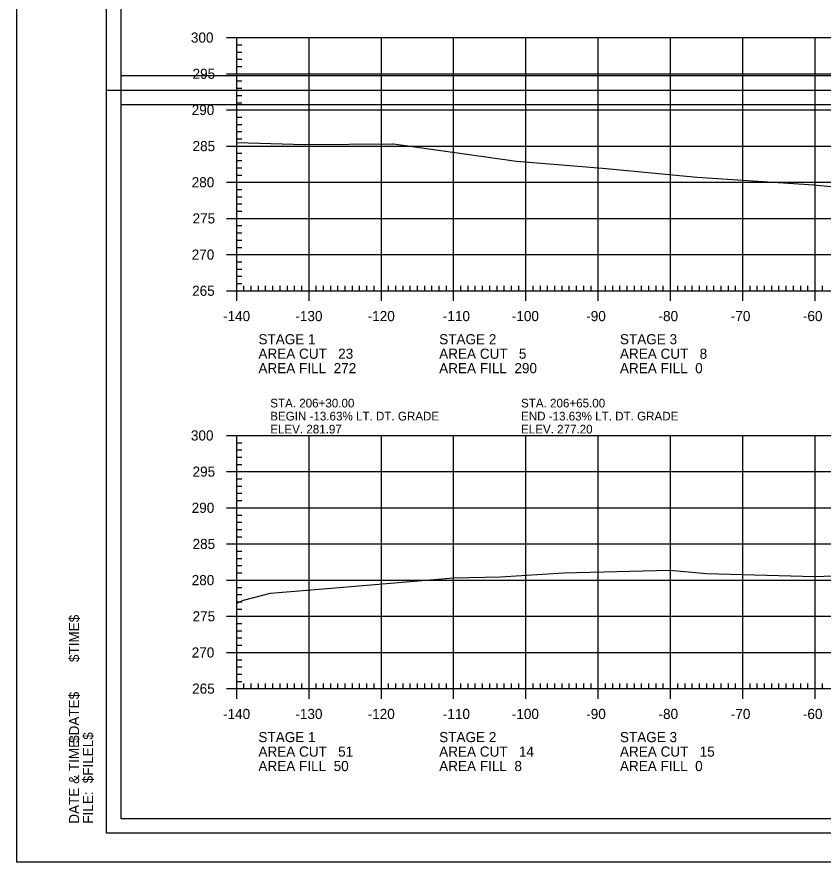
# Model space of a CAD drawing. Extents: x 1368713 to 1370673, y 380279 to 380950.
# Drawn here: x 1370339.2 to 1370450.7, y 380523.8 to 380640.6 of the extents above; entities that cross this region are included whole.
import ezdxf

# ---------------------------------------------------------------- set-up
doc = ezdxf.new("R2010")
doc.units = 0
for name, color, linetype in [('Notes', 7, 'Continuous'), ('R_Axis', 7, 'Continuous'), ('R_Axis Annot', 7, 'Continuous'), ('R_Border', 7, 'Continuous'), ('R_Border Notes', 7, 'Continuous'), ('R_Border Plan-Plan', 7, 'Continuous'), ('R_Exist Surface', 7, 'Continuous'), ('R_Grid', 7, 'Continuous'), ('R_No Plot', 7, 'Continuous')]:
    doc.layers.add(name, color=color, linetype=linetype)

msp = doc.modelspace()

# ---------------------------------------------------------------- linework, layer by layer
at = {"layer": 'R_Axis'}
for p, q in [((1370368.23, 380637.75), (1370371.03, 380637.75)), ((1370369.63, 380602.75), (1370369.63, 380637.75)), ((1370369.63, 380636.75), (1370370.33, 380636.75)), ((1370369.63, 380635.75), (1370370.33, 380635.75)), ((1370369.63, 380634.75), (1370370.33, 380634.75)), ((1370369.63, 380633.75), (1370370.33, 380633.75)), ((1370368.23, 380632.75), (1370371.03, 380632.75)), ((1370369.63, 380631.75), (1370370.33, 380631.75)), ((1370369.63, 380630.75), (1370370.33, 380630.75)), ((1370369.63, 380629.75), (1370370.33, 380629.75)), ((1370369.63, 380628.75), (1370370.33, 380628.75)), ((1370368.23, 380627.75), (1370371.03, 380627.75)), ((1370369.63, 380626.75), (1370370.33, 380626.75)), ((1370369.63, 380625.75), (1370370.33, 380625.75)), ((1370369.63, 380624.75), (1370370.33, 380624.75)), ((1370369.63, 380623.75), (1370370.33, 380623.75)), ((1370368.23, 380622.75), (1370371.03, 380622.75)), ((1370369.63, 380621.75), (1370370.33, 380621.75)), ((1370369.63, 380620.75), (1370370.33, 380620.75)), ((1370369.63, 380619.75), (1370370.33, 380619.75)), ((1370369.63, 380618.75), (1370370.33, 380618.75)), ((1370368.23, 380617.75), (1370371.03, 380617.75)), ((1370369.63, 380616.75), (1370370.33, 380616.75)), ((1370369.63, 380615.75), (1370370.33, 380615.75)), ((1370369.63, 380614.75), (1370370.33, 380614.75)), ((1370369.63, 380613.75), (1370370.33, 380613.75)), ((1370368.23, 380612.75), (1370371.03, 380612.75)), ((1370369.63, 380611.75), (1370370.33, 380611.75)), ((1370369.63, 380610.75), (1370370.33, 380610.75)), ((1370369.63, 380609.75), (1370370.33, 380609.75)), ((1370368.23, 380607.75), (1370371.03, 380607.75)), ((1370369.63, 380608.75), (1370370.33, 380608.75)), ((1370369.63, 380606.75), (1370370.33, 380606.75)), ((1370369.63, 380605.75), (1370370.33, 380605.75)), ((1370369.63, 380604.75), (1370370.33, 380604.75)), ((1370369.63, 380601.35), (1370369.63, 380604.15)), ((1370379.63, 380601.35), (1370379.63, 380604.15)), ((1370389.63, 380601.35), (1370389.63, 380604.15)), ((1370399.63, 380601.35), (1370399.63, 380604.15)), ((1370409.63, 380601.35), (1370409.63, 380604.15)), ((1370419.63, 380601.35), (1370419.63, 380604.15)), ((1370429.63, 380601.35), (1370429.63, 380604.15)), ((1370439.63, 380601.35), (1370439.63, 380604.15)), ((1370449.63, 380601.35), (1370449.63, 380604.15)), ((1370369.63, 380603.75), (1370370.33, 380603.75)), ((1370370.63, 380602.75), (1370370.63, 380603.45)), ((1370371.63, 380602.75), (1370371.63, 380603.45)), ((1370372.63, 380602.75), (1370372.63, 380603.45)), ((1370373.63, 380602.75), (1370373.63, 380603.45)), ((1370374.63, 380602.75), (1370374.63, 380603.45)), ((1370375.63, 380602.75), (1370375.63, 380603.45)), ((1370376.63, 380602.75), (1370376.63, 380603.45)), ((1370377.63, 380602.75), (1370377.63, 380603.45)), ((1370378.63, 380602.75), (1370378.63, 380603.45)), ((1370380.63, 380602.75), (1370380.63, 380603.45)), ((1370381.63, 380602.75), (1370381.63, 380603.45)), ((1370382.63, 380602.75), (1370382.63, 380603.45)), ((1370383.63, 380602.75), (1370383.63, 380603.45)), ((1370384.63, 380602.75), (1370384.63, 380603.45)), ((1370385.63, 380602.75), (1370385.63, 380603.45)), ((1370386.63, 380602.75), (1370386.63, 380603.45)), ((1370387.63, 380602.75), (1370387.63, 380603.45)), ((1370388.63, 380602.75), (1370388.63, 380603.45)), ((1370390.63, 380602.75), (1370390.63, 380603.45)), ((1370391.63, 380602.75), (1370391.63, 380603.45)), ((1370392.63, 380602.75), (1370392.63, 380603.45)), ((1370393.63, 380602.75), (1370393.63, 380603.45)), ((1370394.63, 380602.75), (1370394.63, 380603.45)), ((1370395.63, 380602.75), (1370395.63, 380603.45)), ((1370396.63, 380602.75), (1370396.63, 380603.45)), ((1370397.63, 380602.75), (1370397.63, 380603.45)), ((1370398.63, 380602.75), (1370398.63, 380603.45)), ((1370400.63, 380602.75), (1370400.63, 380603.45)), ((1370401.63, 380602.75), (1370401.63, 380603.45)), ((1370402.63, 380602.75), (1370402.63, 380603.45)), ((1370403.63, 380602.75), (1370403.63, 380603.45)), ((1370404.63, 380602.75), (1370404.63, 380603.45)), ((1370405.63, 380602.75), (1370405.63, 380603.45)), ((1370406.63, 380602.75), (1370406.63, 380603.45)), ((1370407.63, 380602.75), (1370407.63, 380603.45)), ((1370408.63, 380602.75), (1370408.63, 380603.45)), ((1370410.63, 380602.75), (1370410.63, 380603.45)), ((1370411.63, 380602.75), (1370411.63, 380603.45)), ((1370412.63, 380602.75), (1370412.63, 380603.45)), ((1370413.63, 380602.75), (1370413.63, 380603.45)), ((1370414.63, 380602.75), (1370414.63, 380603.45)), ((1370415.63, 380602.75), (1370415.63, 380603.45)), ((1370416.63, 380602.75), (1370416.63, 380603.45)), ((1370417.63, 380602.75), (1370417.63, 380603.45)), ((1370418.63, 380602.75), (1370418.63, 380603.45)), ((1370420.63, 380602.75), (1370420.63, 380603.45)), ((1370421.63, 380602.75), (1370421.63, 380603.45)), ((1370422.63, 380602.75), (1370422.63, 380603.45)), ((1370423.63, 380602.75), (1370423.63, 380603.45)), ((1370424.63, 380602.75), (1370424.63, 380603.45)), ((1370425.63, 380602.75), (1370425.63, 380603.45)), ((1370426.63, 380602.75), (1370426.63, 380603.45)), ((1370427.63, 380602.75), (1370427.63, 380603.45)), ((1370428.63, 380602.75), (1370428.63, 380603.45)), ((1370430.63, 380602.75), (1370430.63, 380603.45)), ((1370431.63, 380602.75), (1370431.63, 380603.45)), ((1370432.63, 380602.75), (1370432.63, 380603.45)), ((1370433.63, 380602.75), (1370433.63, 380603.45)), ((1370434.63, 380602.75), (1370434.63, 380603.45)), ((1370435.63, 380602.75), (1370435.63, 380603.45)), ((1370436.63, 380602.75), (1370436.63, 380603.45)), ((1370437.63, 380602.75), (1370437.63, 380603.45)), ((1370438.63, 380602.75), (1370438.63, 380603.45)), ((1370440.63, 380602.75), (1370440.63, 380603.45)), ((1370441.63, 380602.75), (1370441.63, 380603.45)), ((1370442.63, 380602.75), (1370442.63, 380603.45)), ((1370443.63, 380602.75), (1370443.63, 380603.45)), ((1370444.63, 380602.75), (1370444.63, 380603.45)), ((1370445.63, 380602.75), (1370445.63, 380603.45)), ((1370446.63, 380602.75), (1370446.63, 380603.45)), ((1370447.63, 380602.75), (1370447.63, 380603.45)), ((1370448.63, 380602.75), (1370448.63, 380603.45)), ((1370450.63, 380602.75), (1370450.63, 380603.45)), ((1370368.23, 380602.75), (1370371.03, 380602.75)), ((1370369.63, 380602.75), (1370649.63, 380602.75)), ((1370368.23, 380582.75), (1370371.03, 380582.75)), ((1370369.63, 380547.75), (1370369.63, 380582.75)), ((1370369.63, 380581.75), (1370370.33, 380581.75)), ((1370369.63, 380580.75), (1370370.33, 380580.75)), ((1370369.63, 380579.75), (1370370.33, 380579.75)), ((1370369.63, 380578.75), (1370370.33, 380578.75)), ((1370368.23, 380577.75), (1370371.03, 380577.75)), ((1370369.63, 380576.75), (1370370.33, 380576.75)), ((1370369.63, 380575.75), (1370370.33, 380575.75)), ((1370369.63, 380574.75), (1370370.33, 380574.75)), ((1370368.23, 380572.75), (1370371.03, 380572.75)), ((1370369.63, 380573.75), (1370370.33, 380573.75)), ((1370369.63, 380571.75), (1370370.33, 380571.75)), ((1370369.63, 380570.75), (1370370.33, 380570.75)), ((1370369.63, 380569.75), (1370370.33, 380569.75)), ((1370369.63, 380568.75), (1370370.33, 380568.75)), ((1370368.23, 380567.75), (1370371.03, 380567.75)), ((1370369.63, 380566.75), (1370370.33, 380566.75)), ((1370369.63, 380565.75), (1370370.33, 380565.75)), ((1370369.63, 380564.75), (1370370.33, 380564.75)), ((1370369.63, 380563.75), (1370370.33, 380563.75)), ((1370368.23, 380562.75), (1370371.03, 380562.75)), ((1370369.63, 380561.75), (1370370.33, 380561.75)), ((1370369.63, 380560.75), (1370370.33, 380560.75)), ((1370369.63, 380559.75), (1370370.33, 380559.75)), ((1370369.63, 380558.75), (1370370.33, 380558.75)), ((1370368.23, 380557.75), (1370371.03, 380557.75)), ((1370369.63, 380556.75), (1370370.33, 380556.75)), ((1370369.63, 380555.75), (1370370.33, 380555.75)), ((1370369.63, 380554.75), (1370370.33, 380554.75)), ((1370368.23, 380552.75), (1370371.03, 380552.75)), ((1370369.63, 380553.75), (1370370.33, 380553.75)), ((1370369.63, 380551.75), (1370370.33, 380551.75)), ((1370369.63, 380550.75), (1370370.33, 380550.75)), ((1370369.63, 380549.75), (1370370.33, 380549.75)), ((1370369.63, 380546.35), (1370369.63, 380549.15)), ((1370369.63, 380548.75), (1370370.33, 380548.75)), ((1370370.63, 380547.75), (1370370.63, 380548.45)), ((1370371.63, 380547.75), (1370371.63, 380548.45)), ((1370372.63, 380547.75), (1370372.63, 380548.45)), ((1370373.63, 380547.75), (1370373.63, 380548.45)), ((1370374.63, 380547.75), (1370374.63, 380548.45)), ((1370375.63, 380547.75), (1370375.63, 380548.45)), ((1370376.63, 380547.75), (1370376.63, 380548.45)), ((1370377.63, 380547.75), (1370377.63, 380548.45)), ((1370378.63, 380547.75), (1370378.63, 380548.45)), ((1370379.63, 380546.35), (1370379.63, 380549.15)), ((1370380.63, 380547.75), (1370380.63, 380548.45)), ((1370381.63, 380547.75), (1370381.63, 380548.45)), ((1370382.63, 380547.75), (1370382.63, 380548.45)), ((1370383.63, 380547.75), (1370383.63, 380548.45)), ((1370384.63, 380547.75), (1370384.63, 380548.45)), ((1370385.63, 380547.75), (1370385.63, 380548.45)), ((1370386.63, 380547.75), (1370386.63, 380548.45)), ((1370387.63, 380547.75), (1370387.63, 380548.45)), ((1370388.63, 380547.75), (1370388.63, 380548.45)), ((1370389.63, 380546.35), (1370389.63, 380549.15)), ((1370390.63, 380547.75), (1370390.63, 380548.45)), ((1370391.63, 380547.75), (1370391.63, 380548.45)), ((1370392.63, 380547.75), (1370392.63, 380548.45)), ((1370393.63, 380547.75), (1370393.63, 380548.45)), ((1370394.63, 380547.75), (1370394.63, 380548.45)), ((1370395.63, 380547.75), (1370395.63, 380548.45)), ((1370396.63, 380547.75), (1370396.63, 380548.45)), ((1370397.63, 380547.75), (1370397.63, 380548.45)), ((1370398.63, 380547.75), (1370398.63, 380548.45)), ((1370399.63, 380546.35), (1370399.63, 380549.15)), ((1370400.63, 380547.75), (1370400.63, 380548.45)), ((1370401.63, 380547.75), (1370401.63, 380548.45)), ((1370402.63, 380547.75), (1370402.63, 380548.45)), ((1370403.63, 380547.75), (1370403.63, 380548.45)), ((1370404.63, 380547.75), (1370404.63, 380548.45)), ((1370405.63, 380547.75), (1370405.63, 380548.45)), ((1370406.63, 380547.75), (1370406.63, 380548.45)), ((1370407.63, 380547.75), (1370407.63, 380548.45)), ((1370408.63, 380547.75), (1370408.63, 380548.45)), ((1370409.63, 380546.35), (1370409.63, 380549.15)), ((1370410.63, 380547.75), (1370410.63, 380548.45)), ((1370411.63, 380547.75), (1370411.63, 380548.45)), ((1370412.63, 380547.75), (1370412.63, 380548.45)), ((1370413.63, 380547.75), (1370413.63, 380548.45)), ((1370414.63, 380547.75), (1370414.63, 380548.45)), ((1370415.63, 380547.75), (1370415.63, 380548.45)), ((1370416.63, 380547.75), (1370416.63, 380548.45)), ((1370417.63, 380547.75), (1370417.63, 380548.45)), ((1370418.63, 380547.75), (1370418.63, 380548.45)), ((1370419.63, 380546.35), (1370419.63, 380549.15)), ((1370420.63, 380547.75), (1370420.63, 380548.45)), ((1370421.63, 380547.75), (1370421.63, 380548.45)), ((1370422.63, 380547.75), (1370422.63, 380548.45)), ((1370423.63, 380547.75), (1370423.63, 380548.45)), ((1370424.63, 380547.75), (1370424.63, 380548.45)), ((1370425.63, 380547.75), (1370425.63, 380548.45)), ((1370426.63, 380547.75), (1370426.63, 380548.45)), ((1370427.63, 380547.75), (1370427.63, 380548.45)), ((1370428.63, 380547.75), (1370428.63, 380548.45)), ((1370429.63, 380546.35), (1370429.63, 380549.15)), ((1370430.63, 380547.75), (1370430.63, 380548.45)), ((1370431.63, 380547.75), (1370431.63, 380548.45)), ((1370432.63, 380547.75), (1370432.63, 380548.45)), ((1370433.63, 380547.75), (1370433.63, 380548.45)), ((1370434.63, 380547.75), (1370434.63, 380548.45)), ((1370435.63, 380547.75), (1370435.63, 380548.45)), ((1370436.63, 380547.75), (1370436.63, 380548.45)), ((1370437.63, 380547.75), (1370437.63, 380548.45)), ((1370438.63, 380547.75), (1370438.63, 380548.45)), ((1370439.63, 380546.35), (1370439.63, 380549.15)), ((1370440.63, 380547.75), (1370440.63, 380548.45)), ((1370441.63, 380547.75), (1370441.63, 380548.45)), ((1370442.63, 380547.75), (1370442.63, 380548.45)), ((1370443.63, 380547.75), (1370443.63, 380548.45)), ((1370444.63, 380547.75), (1370444.63, 380548.45)), ((1370445.63, 380547.75), (1370445.63, 380548.45)), ((1370446.63, 380547.75), (1370446.63, 380548.45)), ((1370447.63, 380547.75), (1370447.63, 380548.45)), ((1370448.63, 380547.75), (1370448.63, 380548.45)), ((1370449.63, 380546.35), (1370449.63, 380549.15)), ((1370450.63, 380547.75), (1370450.63, 380548.45)), ((1370368.23, 380547.75), (1370371.03, 380547.75)), ((1370369.63, 380547.75), (1370649.63, 380547.75))]:
    msp.add_line(p, q, dxfattribs=at)
at = {"layer": 'R_Border'}
for p, q in [((1370351.63, 380527.75), (1370351.63, 380733.21)), ((1370351.63, 380527.75), (1370351.63, 380527.75)), ((1370667.81, 380527.75), (1370351.63, 380527.75))]:
    msp.add_line(p, q, dxfattribs=at)
at = {"layer": 'R_Border Plan-Plan'}
msp.add_line((1370351.63, 380630.48), (1370667.81, 380630.48), dxfattribs=at)
at = {"layer": 'R_Exist Surface'}
for points in [[(1370369.63, 380623.25), (1370379.05, 380622.96), (1370391.21, 380623.05), (1370391.27, 380623.05), (1370391.3, 380623.05), (1370408.33, 380620.66), (1370420.22, 380619.72), (1370433.29, 380618.44), (1370449.47, 380617.4), (1370451.79, 380617.16)], [(1370369.63, 380559.56), (1370370.55, 380559.99), (1370374.3, 380560.93), (1370384.91, 380561.8), (1370399.59, 380563.05), (1370406.13, 380563.21), (1370414.83, 380563.74), (1370429.53, 380564.12), (1370434.61, 380563.68), (1370449.57, 380563.26), (1370452.15, 380563.35)]]:
    msp.add_lwpolyline(points, dxfattribs=at)
at = {"layer": 'R_Grid'}
for p, q in [((1370369.63, 380637.75), (1370649.63, 380637.75)), ((1370369.63, 380602.75), (1370369.63, 380637.75)), ((1370379.63, 380602.75), (1370379.63, 380637.75)), ((1370389.63, 380602.75), (1370389.63, 380637.75)), ((1370399.63, 380602.75), (1370399.63, 380637.75)), ((1370409.63, 380602.75), (1370409.63, 380637.75)), ((1370419.63, 380602.75), (1370419.63, 380637.75)), ((1370429.63, 380602.75), (1370429.63, 380637.75)), ((1370439.63, 380602.75), (1370439.63, 380637.75)), ((1370449.63, 380602.75), (1370449.63, 380637.75)), ((1370369.63, 380632.75), (1370649.63, 380632.75)), ((1370369.63, 380627.75), (1370649.63, 380627.75)), ((1370369.63, 380622.75), (1370649.63, 380622.75)), ((1370369.63, 380617.75), (1370649.63, 380617.75)), ((1370369.63, 380612.75), (1370649.63, 380612.75)), ((1370369.63, 380607.75), (1370649.63, 380607.75)), ((1370369.63, 380602.75), (1370649.63, 380602.75)), ((1370369.63, 380582.75), (1370649.63, 380582.75)), ((1370369.63, 380547.75), (1370369.63, 380582.75)), ((1370379.63, 380547.75), (1370379.63, 380582.75)), ((1370389.63, 380547.75), (1370389.63, 380582.75)), ((1370399.63, 380547.75), (1370399.63, 380582.75)), ((1370409.63, 380547.75), (1370409.63, 380582.75)), ((1370419.63, 380547.75), (1370419.63, 380582.75)), ((1370429.63, 380547.75), (1370429.63, 380582.75)), ((1370439.63, 380547.75), (1370439.63, 380582.75)), ((1370449.63, 380547.75), (1370449.63, 380582.75)), ((1370369.63, 380577.75), (1370649.63, 380577.75)), ((1370369.63, 380572.75), (1370649.63, 380572.75)), ((1370369.63, 380567.75), (1370649.63, 380567.75)), ((1370369.63, 380562.75), (1370649.63, 380562.75)), ((1370369.63, 380557.75), (1370649.63, 380557.75)), ((1370369.63, 380552.75), (1370649.63, 380552.75)), ((1370369.63, 380547.75), (1370649.63, 380547.75))]:
    msp.add_line(p, q, dxfattribs=at)
at = {"layer": 'R_No Plot'}
for points in [[(1370339.22, 380737.11), (1370672.56, 380737.11), (1370672.56, 380523.77), (1370339.22, 380523.77)], [(1370665.81, 380632.48), (1370353.63, 380632.48), (1370353.63, 380731.21), (1370603.17, 380731.21), (1370603.17, 380721.33), (1370620.71, 380721.33), (1370644.81, 380721.33), (1370644.81, 380699), (1370665.81, 380699)], [(1370353.63, 380731.21), (1370603.17, 380731.21), (1370603.17, 380721.33), (1370620.71, 380721.33), (1370644.81, 380721.33), (1370644.81, 380699), (1370665.81, 380699), (1370665.81, 380529.75), (1370353.63, 380529.75)], [(1370353.63, 380628.48), (1370665.81, 380628.48), (1370665.81, 380529.75), (1370353.63, 380529.75)]]:
    msp.add_lwpolyline(points, close=True, dxfattribs=at)

# ---------------------------------------------------------------- texts
at = {"layer": 'Notes'}
for s, p in [('STA. 206+30.00', (1370374.26, 380586.62)), ('STA. 206+65.00', (1370408.95, 380586.62)), ('BEGIN -13.63% LT. DT. GRADE', (1370374.26, 380584.82)), ('END -13.63% LT. DT. GRADE', (1370408.95, 380584.82)), ('ELEV. 281.97', (1370374.26, 380583.02)), ('ELEV. 277.20', (1370408.95, 380583.02))]:
    msp.add_text(s, height=1.2, dxfattribs=at).set_placement(p)
at = {"layer": 'R_Axis Annot'}
for s, p in [('300', (1370363.29, 380637.05)), ('295', (1370363.52, 380632.05)), ('290', (1370363.4, 380627.05)), ('285', (1370363.52, 380622.05)), ('280', (1370363.4, 380617.05)), ('275', (1370363.52, 380612.05)), ('270', (1370363.4, 380607.05)), ('265', (1370363.46, 380602.05)), ('-140', (1370367.74, 380598.55)), ('-130', (1370377.74, 380598.55)), ('-120', (1370387.74, 380598.55)), ('-110', (1370398.14, 380598.55)), ('-100', (1370407.68, 380598.55)), ('-90', (1370417.97, 380598.55)), ('-80', (1370427.97, 380598.55)), ('-70', (1370437.97, 380598.55)), ('-60', (1370447.94, 380598.55)), ('STAGE 1', (1370372.63, 380595.35)), ('STAGE 2', (1370397.63, 380595.35)), ('STAGE 3', (1370422.63, 380595.35)), ('AREA CUT   23', (1370372.63, 380593.35)), ('AREA CUT   5', (1370397.63, 380593.35)), ('AREA CUT   8', (1370422.63, 380593.35)), ('AREA FILL  272', (1370372.63, 380591.35)), ('AREA FILL  290', (1370397.63, 380591.35)), ('AREA FILL  0', (1370422.63, 380591.35)), ('300', (1370363.29, 380582.05)), ('295', (1370363.52, 380577.05)), ('290', (1370363.4, 380572.05)), ('285', (1370363.52, 380567.05)), ('280', (1370363.4, 380562.05)), ('275', (1370363.52, 380557.05)), ('270', (1370363.4, 380552.05)), ('265', (1370363.46, 380547.05)), ('-140', (1370367.74, 380543.55)), ('-130', (1370377.74, 380543.55)), ('-120', (1370387.74, 380543.55)), ('-110', (1370398.14, 380543.55)), ('-100', (1370407.68, 380543.55)), ('-90', (1370417.97, 380543.55)), ('-80', (1370427.97, 380543.55)), ('-70', (1370437.97, 380543.55)), ('-60', (1370447.94, 380543.55)), ('STAGE 1', (1370372.63, 380540.35)), ('STAGE 2', (1370397.63, 380540.35)), ('STAGE 3', (1370422.63, 380540.35)), ('AREA CUT   51', (1370372.63, 380538.35)), ('AREA CUT   14', (1370397.63, 380538.35)), ('AREA CUT   15', (1370422.63, 380538.35)), ('AREA FILL  50', (1370372.63, 380536.35)), ('AREA FILL  8', (1370397.63, 380536.35)), ('AREA FILL  0', (1370422.63, 380536.35))]:
    msp.add_text(s, height=1.4, dxfattribs=at).set_placement(p)
at = {"layer": 'R_Border Notes'}
for s, height, p in [('$TIME$', 1.397, (1370347.83, 380551.42)), ('$DATE$', 1.397, (1370347.83, 380540.25)), ('DATE & TIME:', 1.3968, (1370347.83, 380529.08)), ('$FILEL$', 1.397, (1370349.75, 380534.66)), ('FILE: ', 1.397, (1370349.75, 380529.08))]:
    msp.add_text(s, height=height, rotation=90, dxfattribs=at).set_placement(p)

doc.saveas('drawing.dxf')
